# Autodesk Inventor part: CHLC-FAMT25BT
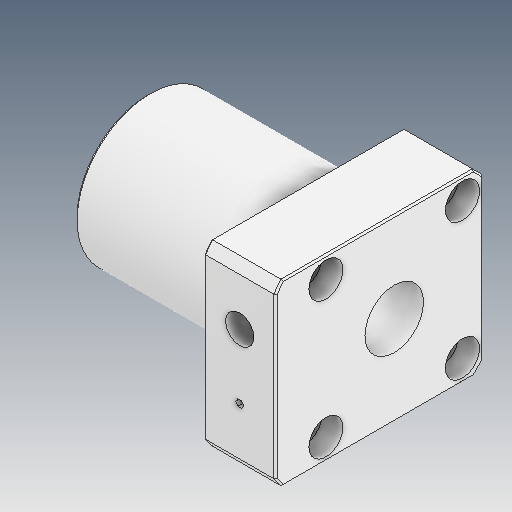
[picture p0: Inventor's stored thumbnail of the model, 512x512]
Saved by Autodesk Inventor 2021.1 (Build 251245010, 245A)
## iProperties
Created: 2021-05
Part Number: CHLC-FAMT25BT
Material: Ogólny
Document SubType Name: Modeling
Designer: user
Density: 1 g/cm^3
Appearance: Domyślna
Author: user
Revision Number: ÈÎºÎ
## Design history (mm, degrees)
feature "ÊäÈë1"
feature "ÊäÈë2"
node "Bryła1"
node "Bryła2"
